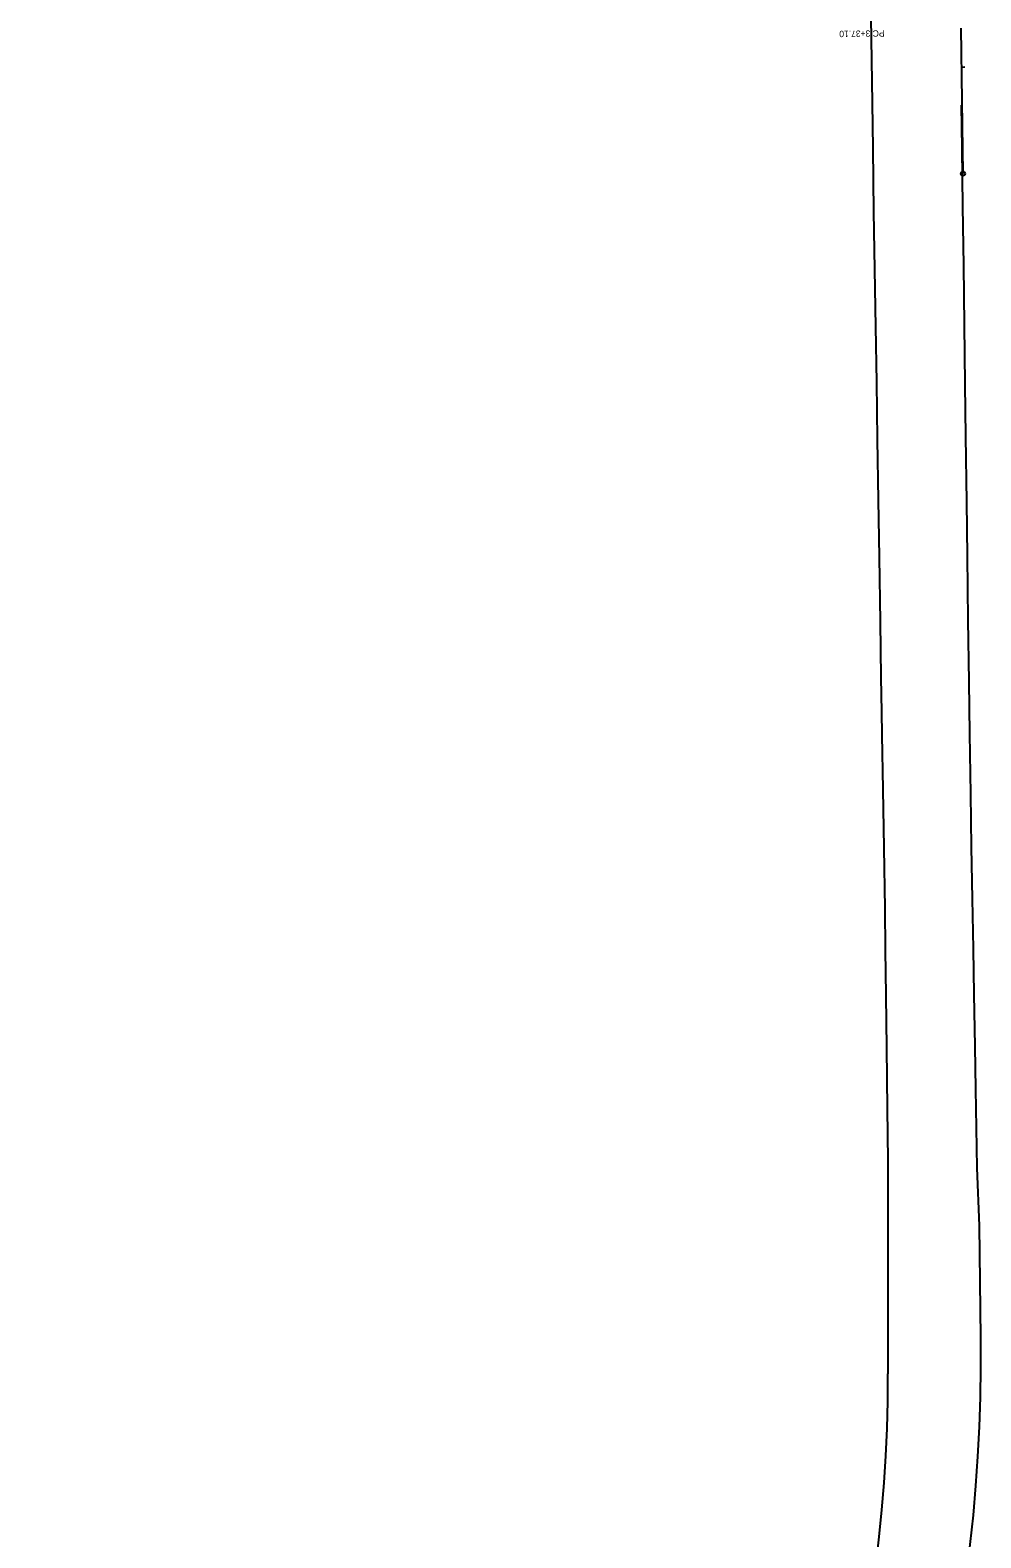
# Model space of a CAD drawing. Extents: x 1665984 to 1683035, y 227409 to 233856.
# Drawn here: x 1676567 to 1677462, y 228829 to 230249 of the extents above; entities that cross this region are included whole.
import ezdxf

# ---------------------------------------------------------------- set-up
doc = ezdxf.new("R2010")
doc.units = 0
for name, color, linetype in [('R_Horz Alg', 7, 'Continuous'), ('R_Horz Alg Annot', 7, 'Continuous'), ('R_No Plot', 7, 'Continuous')]:
    doc.layers.add(name, color=color, linetype=linetype)

msp = doc.modelspace()

# ---------------------------------------------------------------- linework, layer by layer
at = {"layer": 'R_Horz Alg'}
msp.add_line((1677445.5, 230113.6), (1677443.6, 230250.7), dxfattribs=at)
at = {"layer": 'R_Horz Alg Annot'}
msp.add_lwpolyline([(1677447.1, 230213.7), (1677444.1, 230213.6)], dxfattribs=at)
msp.add_circle((1677445.5, 230113.6), 2, dxfattribs=at)
at = {"layer": 'R_No Plot'}
for p, q in [((1677357, 230378), (1677359.8, 230180)), ((1677374.8, 229129.1), (1677374.8, 228983.2))]:
    msp.add_line(p, q, dxfattribs=at)
for points in [[(1677359.8, 230180), (1677360.4, 230137.4), (1677361.3, 230077.7), (1677363.1, 229969.2), (1677363.9, 229917.3), (1677364.7, 229863.3), (1677365.6, 229806.1), (1677366.5, 229752.2), (1677367.4, 229691.5), (1677368.2, 229639.1), (1677368.8, 229606.8), (1677369.1, 229585), (1677369.9, 229533.6), (1677370.8, 229478.5), (1677371.7, 229421.4), (1677372.2, 229382.5), (1677372.7, 229339.4), (1677373.5, 229290.1), (1677374, 229232.8), (1677374.6, 229184.2), (1677374.6, 229173.9), (1677374.8, 229129.1)], [(1677458.7, 229177.3), (1677458.1, 229214.9), (1677457.6, 229251.2), (1677456.8, 229291.8), (1677455.9, 229340.4), (1677455.3, 229383.4), (1677454.3, 229430.6), (1677453.6, 229479.2), (1677452.8, 229529.6), (1677452, 229586), (1677451.3, 229635.4), (1677450.5, 229693.1), (1677449.7, 229753.2), (1677449.1, 229804.4), (1677448.2, 229866), (1677447.6, 229915.3), (1677447, 229971.3), (1677446.3, 230026.9), (1677445.4, 230082.6), (1677444.8, 230137.1), (1677444.2, 230178.2)], [(1677462.2, 229017.3), (1677460.9, 229122.5), (1677458.7, 229177.3)]]:
    msp.add_lwpolyline(points, dxfattribs=at)
for centre, radius, start, end in [((1675910.9, 228998.5), 1551.4, 296.0208, 0.6938), ((1675931.7, 228983.3), 1443.1, 296.104, 359.9977)]:
    msp.add_arc(centre, radius, start, end, dxfattribs=at)

# ---------------------------------------------------------------- texts
at = {"layer": 'R_Horz Alg Annot'}
msp.add_text('PC 3+37.10', height=6, rotation=180.8056, dxfattribs=at).set_placement((1677371.5, 230248.7))

doc.saveas('drawing.dxf')
